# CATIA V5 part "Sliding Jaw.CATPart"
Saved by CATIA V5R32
Part number: Sliding Jaw
Bounding box of the stored display mesh (mm): x -32 to 32, y -16 to 16, z -9 to 36
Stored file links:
  D:\PROJECTS\Project 2022\CATIA V5 6R 2022\Resources\Part Files\c12_catia_v5_6r2022_prt\c12_catia_v5-6r2022 figr_12-19\Sliding Jaw.CATPart
  C:\Program Files\Dassault Systemes\B09\intel_a\reffiles\standard\MetricThickPitch.txt
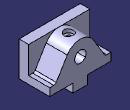
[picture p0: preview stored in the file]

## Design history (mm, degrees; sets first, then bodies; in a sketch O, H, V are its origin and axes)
Body1 (main body)
  Sketch1 on xy-plane, origin (0, 0, 0), H (1, 0, 0), V (0, 1, 0)
    line L1 (-32, -16) -> (32, -16)
    line L2 (32, -16) -> (32, 16)
    line L3 (32, 16) -> (-32, 16)
    line L4 (-32, 16) -> (-32, -16)
    distance H L1 = 16
    distance V L4 = 32
    length L4 = 32
    length L1 = 64
    horizontal: L1 H, L3 H
    vertical: L2 V, L4 V
  Pad1: profile Sketch1, direction (0, 0, 1), length 8
  Sketch2 on face of Pad1, origin (0, -16, 0), H (1, 0, 0), V (0, 0, 1)
    point P1 (-32, 0)
    line L1 (-32, 0) -> (32, 0)
    line L2 (32, 0) -> (32, 36)
    line L3 (32, 36) -> (-32, 36)
    line L4 (-32, 36) -> (-32, 0)
    reference projected line E1 (32, 0) -> (32, 8) from edge of Pad1
    reference projected line E2 (-32, 8) -> (-32, 0) from edge of Pad1
    length L2 = 36
    coincidence: P1 H, L2 E1, L4 E2
    horizontal: L1 H, L3 H
    vertical: L2 V, L4 V
  Pad2: profile Sketch2, direction (0, 1, 0), length 10
  Sketch3 on face of Pad1, origin (0, 16, 0), H (-1, 0, 0), V (0, 0, 1)
    arc A1 centre (0, 20) radius 16 from (13.6777, 28.3018) to (-13.6777, 28.3018) ccw
    point P1 (0, 20)
    reference projected line E1 (-32, 36) -> (32, 36) from edge of Pad2
    line L1 (-26, 8) -> (-13.6777, 28.3018)
    point P2 (-26, 8)
    line L2 (13.6777, 28.3018) -> (26, 8)
    point P3 (26, 8)
    reference projected line E2 (32, 8) -> (-32, 8) from edge of Pad1
    reference projected line E3 (32, 8) -> (-32, 8) from edge of Pad1
    line L3 (-26, 8) -> (26, 8)
    radius A1 = 16
    length L3 = 52
    distance V P3 = 26
    coincidence: P1 V, E2 P2, E3 P3
    tangency: A1 E1, L2 A1, L1 A1
    horizontal: L3 H
  Pad3: profile Sketch3, direction (0, -1, 0), up to the existing solid (limit type 2)
  Fillet1: radius 3, on 2 edges
  Sketch4 on face of Pad1, origin (-2.6964, 16, 22.8197), H (1, 0, 0), V (0, 0, -1)
    point P1 (2.6964, 2.8197)
    reference projected arc E1 centre (2.6964, 2.8197) radius 16 from (-10.9814, -5.4821) to (16.3741, -5.4821) ccw from edge of Pad3
    concentricity: P1 E1
  Hole1: placed by Sketch4, at (0, 16, 20) direction (0, -1, 0), diameter 12, depth 22, V-bottom angle 120
  Sketch5 on face of Pad1, origin (0, 16, 0), H (-1, 0, 0), V (0, 0, 1)
    point P1 (-7.75, 0)
    line L1 (-7.75, 0) -> (7.75, 0)
    line L2 (7.75, 0) -> (7.75, -9)
    line L3 (7.75, -9) -> (-7.75, -9)
    line L4 (-7.75, -9) -> (-7.75, 0)
    distance V L2 = 7.75
    length L3 = 15.5
    length L4 = 9
    coincidence: P1 H
    horizontal: L1 H, L3 H
    vertical: L2 V, L4 V
  Pad4: profile Sketch5, direction (0, -1, 0), length 32
  Sketch6 on face of Pad4, origin (-0.598, -1.2346, -9), H (1, 0, 0), V (0, -1, 0)
    point P1 (0.598, -9.2346)
    reference projected line E1 (8.348, -17.2346) -> (-7.152, -17.2346) from edge of Pad4
    reference projected line E2 (8.348, 14.7654) -> (8.348, -17.2346) from edge of Pad4
    distance P1 E1 = 8
    distance P1 E2 = 7.75
  Hole2: placed by Sketch6, at (0, 8, -9) direction (0, 0, 1), diameter 5, depth 16, V-bottom angle 120, threaded, thread diameter 6, thread depth 16, pitch 1
  RectPattern1: of Hole2, direction 1 instances 2, spacing 16, along edge of Pad4 reversed
  Sketch7 on face of Pad2, origin (-19.6018, -13.7351, 36), H (1, 0, 0), V (0, 1, 0)
    point P1 (19.6018, 17.7351)
    reference intersected line E1 through (19.6018, 0) direction (0, 1) from yz-plane
    reference projected line E2 (51.6018, -2.2649) -> (-12.3982, -2.2649) from edge of Pad2
    distance P1 E2 = 20
    coincidence: E1 P1
  Hole3: placed by Sketch7, at (0, 4, 36) direction (0, 0, -1), diameter 5, depth 16, V-bottom angle 120, counterbore diameter 10, counterbore depth 4, threaded, thread diameter 6, thread depth 11, pitch 1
